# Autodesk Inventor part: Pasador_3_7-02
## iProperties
Created: 2008-01
Part Number: Pasador_3_7-02
Material: Default
Document SubType Name: Modeling
Designer: eruiz-tagle
Mass: 0.846381 g
Surface Area: 10.4091 cm^2
Volume: 0.846381 cm^3
Density: 1 g/cm^3
Author: eruiz-tagle
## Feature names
1. Derived Body1 [Tagging]
